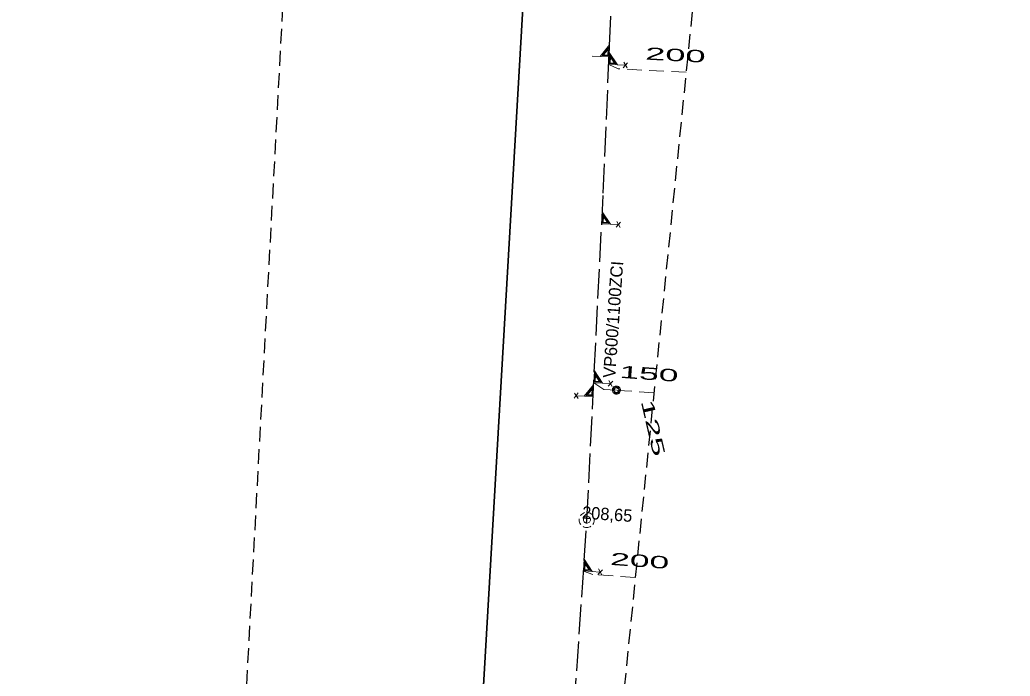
# Model space of a CAD drawing. Extents: x -744446 to -743929, y -1041261 to -1040599.
# Drawn here: x -744445.1 to -744380.7, y -1041003.3 to -1040960.6 of the extents above; entities that cross this region are included whole.
import ezdxf

# ---------------------------------------------------------------- set-up
doc = ezdxf.new("R2010")
doc.units = 0
doc.header["$LTSCALE"] = 0.32
doc.linetypes.add('LONG_DASHED', pattern=[7.5, 6, -1.5])
doc.linetypes.add('MEDIUM_DASHED', pattern=[4.5, 3, -1.5])
for name, color, linetype, lineweight in [('1', 7, 'MEDIUM_DASHED', 25), ('18', 7, 'Continuous', 13), ('20', 7, 'LONG_DASHED', 13), ('49', 7, 'MEDIUM_DASHED', 13)]:
    doc.layers.add(name, color=color, linetype=linetype, lineweight=lineweight)

msp = doc.modelspace()

# ---------------------------------------------------------------- linework, layer by layer
at = {"layer": '1'}
msp.add_lwpolyline([(-744438.077, -1041259.731), (-744438.679, -1041250.888), (-744445.125, -1041198.426), (-744434.434, -1041080.103), (-744426.87, -1040938.41), (-744425.446, -1040859.072), (-744414.192, -1040822.094), (-744390.076, -1040771.45), (-744357.118, -1040726.434), (-744307.278, -1040693.475), (-744241.36, -1040670.967), (-743937.498, -1040598.618), (-743928.655, -1040619.519), (-744129.684, -1040665.585), (-744218.109, -1040687.29), (-744311.358, -1040718.641), (-744361.198, -1040777.323), (-744391.745, -1040864.141), (-744411.355, -1041059.185), (-744416.379, -1041145.154), (-744432.569, -1041193.163), (-744432.047, -1041202.053), (-744422.803, -1041230.992), (-744424.813, -1041260.936)], close=True, dxfattribs=at)
at = {"layer": '18'}
for p, q in [((-744405.591, -1040963.438), (-744405.874, -1040963.761)), ((-744405.617, -1040963.775), (-744405.845, -1040963.394)), ((-744406.047, -1040973.806), (-744406.333, -1040974.127)), ((-744406.076, -1040974.143), (-744406.301, -1040973.76)), ((-744406.566, -1040984.143), (-744406.852, -1040984.464)), ((-744406.595, -1040984.48), (-744406.82, -1040984.097)), ((-744409.062, -1040985.256), (-744408.8, -1040984.898)), ((-744409.058, -1040984.917), (-744408.806, -1040985.265)), ((-744407.234, -1040996.401), (-744407.524, -1040996.718)), ((-744407.268, -1040996.738), (-744407.487, -1040996.351))]:
    msp.add_line(p, q, dxfattribs=at)
for points in [[(-744407.89, -1040963), (-744406.795, -1040963.047), (-744406.762, -1040962.276), (-744407.372, -1040963.022)], [(-744407.252, -1040962.976), (-744406.837, -1040962.994), (-744406.812, -1040962.429), (-744407.253, -1040962.976)], [(-744407.166, -1040962.933), (-744406.876, -1040962.945), (-744406.86, -1040962.574), (-744407.166, -1040962.934)], [(-744405.727, -1040963.592), (-744406.821, -1040963.545), (-744406.788, -1040962.776), (-744406.243, -1040963.57)], [(-744406.36, -1040963.515), (-744406.775, -1040963.497), (-744406.751, -1040962.932), (-744406.358, -1040963.515)], [(-744406.441, -1040963.465), (-744406.733, -1040963.452), (-744406.717, -1040963.08), (-744406.441, -1040963.466)], [(-744406.184, -1040973.959), (-744407.278, -1040973.904), (-744407.239, -1040973.135), (-744406.7, -1040973.933)], [(-744406.817, -1040973.878), (-744407.231, -1040973.857), (-744407.203, -1040973.291), (-744406.815, -1040973.878)], [(-744406.897, -1040973.826), (-744407.189, -1040973.812), (-744407.17, -1040973.44), (-744406.897, -1040973.827)], [(-744406.703, -1040984.296), (-744407.797, -1040984.241), (-744407.758, -1040983.472), (-744407.219, -1040984.27)], [(-744407.336, -1040984.215), (-744407.75, -1040984.194), (-744407.722, -1040983.628), (-744407.334, -1040984.215)], [(-744407.416, -1040984.163), (-744407.708, -1040984.149), (-744407.689, -1040983.777), (-744407.416, -1040984.164)], [(-744408.937, -1040985.084), (-744407.843, -1040985.139), (-744407.804, -1040984.369), (-744408.42, -1040985.11)], [(-744408.3, -1040985.065), (-744407.884, -1040985.086), (-744407.856, -1040984.522), (-744408.301, -1040985.065)], [(-744408.213, -1040985.023), (-744407.923, -1040985.037), (-744407.904, -1040984.667), (-744408.213, -1040985.025)], [(-744408.396, -1040992.69), (-744408.467, -1040992.718), (-744408.534, -1040992.757), (-744408.594, -1040992.805), (-744408.645, -1040992.862), (-744408.669, -1040992.896)], [(-744407.855, -1040992.873), (-744407.905, -1040992.815), (-744407.963, -1040992.765), (-744408.028, -1040992.724), (-744408.099, -1040992.695), (-744408.148, -1040992.681)], [(-744408.741, -1040993.082), (-744408.747, -1040993.159), (-744408.742, -1040993.236), (-744408.725, -1040993.311), (-744408.696, -1040993.382), (-744408.656, -1040993.448), (-744408.64, -1040993.47)], [(-744408.483, -1040993.599), (-744408.413, -1040993.63), (-744408.338, -1040993.649), (-744408.262, -1040993.656), (-744408.185, -1040993.651), (-744408.11, -1040993.634), (-744408.038, -1040993.606), (-744407.978, -1040993.571)], [(-744407.86, -1040993.459), (-744407.819, -1040993.394), (-744407.788, -1040993.324), (-744407.769, -1040993.249), (-744407.761, -1040993.173), (-744407.766, -1040993.096), (-744407.772, -1040993.061)], [(-744407.373, -1040996.552), (-744408.466, -1040996.479), (-744408.414, -1040995.711), (-744407.889, -1040996.518)], [(-744408.004, -1040996.46), (-744408.418, -1040996.432), (-744408.381, -1040995.868), (-744408.002, -1040996.46)], [(-744408.084, -1040996.408), (-744408.375, -1040996.388), (-744408.351, -1040996.017), (-744408.084, -1040996.409)]]:
    msp.add_lwpolyline(points, dxfattribs=at)
for points in [[(-744406.057, -1040984.722), (-744406.063, -1040984.666), (-744406.08, -1040984.613), (-744406.108, -1040984.564), (-744406.147, -1040984.523), (-744406.193, -1040984.491), (-744406.245, -1040984.469), (-744406.3, -1040984.458), (-744406.356, -1040984.46), (-744406.411, -1040984.473), (-744406.462, -1040984.498), (-744406.506, -1040984.533), (-744406.542, -1040984.576), (-744406.567, -1040984.626), (-744406.582, -1040984.681), (-744406.585, -1040984.737), (-744406.576, -1040984.792), (-744406.555, -1040984.845), (-744406.524, -1040984.891), (-744406.483, -1040984.93), (-744406.436, -1040984.96), (-744406.383, -1040984.979), (-744406.327, -1040984.986), (-744406.271, -1040984.982), (-744406.217, -1040984.965), (-744406.168, -1040984.938), (-744406.126, -1040984.9), (-744406.093, -1040984.855), (-744406.07, -1040984.804), (-744406.058, -1040984.749)], [(-744406.116, -1040984.725), (-744406.122, -1040984.676), (-744406.14, -1040984.63), (-744406.168, -1040984.589), (-744406.205, -1040984.556), (-744406.249, -1040984.534), (-744406.297, -1040984.522), (-744406.346, -1040984.522), (-744406.394, -1040984.534), (-744406.438, -1040984.557), (-744406.475, -1040984.59), (-744406.503, -1040984.631), (-744406.52, -1040984.678), (-744406.526, -1040984.727), (-744406.519, -1040984.776), (-744406.501, -1040984.822), (-744406.473, -1040984.862), (-744406.436, -1040984.895), (-744406.392, -1040984.917), (-744406.343, -1040984.929), (-744406.294, -1040984.928), (-744406.246, -1040984.916), (-744406.203, -1040984.892), (-744406.166, -1040984.859), (-744406.138, -1040984.818), (-744406.122, -1040984.771)], [(-744406.175, -1040984.729), (-744406.181, -1040984.687), (-744406.198, -1040984.649), (-744406.226, -1040984.618), (-744406.261, -1040984.595), (-744406.301, -1040984.584), (-744406.343, -1040984.584), (-744406.383, -1040984.596), (-744406.418, -1040984.619), (-744406.445, -1040984.651), (-744406.462, -1040984.689), (-744406.467, -1040984.73), (-744406.461, -1040984.772), (-744406.443, -1040984.809), (-744406.415, -1040984.841), (-744406.379, -1040984.863), (-744406.339, -1040984.874), (-744406.297, -1040984.873), (-744406.257, -1040984.86), (-744406.223, -1040984.837), (-744406.196, -1040984.804), (-744406.18, -1040984.766)], [(-744408.012, -1040993.142), (-744408.018, -1040993.09), (-744408.036, -1040993.04), (-744408.064, -1040992.996), (-744408.102, -1040992.959), (-744408.147, -1040992.932), (-744408.197, -1040992.916), (-744408.249, -1040992.911), (-744408.301, -1040992.918), (-744408.35, -1040992.937), (-744408.394, -1040992.967), (-744408.429, -1040993.006), (-744408.455, -1040993.051), (-744408.47, -1040993.102), (-744408.473, -1040993.154), (-744408.465, -1040993.206), (-744408.444, -1040993.254), (-744408.414, -1040993.297), (-744408.374, -1040993.332), (-744408.328, -1040993.356), (-744408.277, -1040993.37), (-744408.225, -1040993.372), (-744408.173, -1040993.362), (-744408.125, -1040993.34), (-744408.083, -1040993.308), (-744408.05, -1040993.268), (-744408.026, -1040993.221), (-744408.014, -1040993.17)]]:
    msp.add_lwpolyline(points, close=True, dxfattribs=at)
at = {"layer": '20', "lineweight": 25}
msp.add_line((-744410.659, -1041029.321), (-744408.243, -1040993.153), dxfattribs=at)
at = {"layer": '20', "linetype": 'Continuous', "lineweight": 35}
msp.add_lwpolyline([(-744429.62, -1041252.21), (-744428.789, -1041237.94), (-744437.959, -1041195.193), (-744423.3, -1041145.69), (-744417.879, -1041053.98), (-744409.949, -1040917.67), (-744407.76, -1040880.01), (-744407.219, -1040869.23), (-744404.395, -1040847.829), (-744400.25, -1040827.35), (-744393.491, -1040807.621), (-744384.879, -1040787.9), (-744372.238, -1040768.547), (-744361.26, -1040752.62), (-744345.317, -1040736.555), (-744330.739, -1040723.14), (-744312.333, -1040710.859), (-744294.67, -1040700.75), (-744274.728, -1040692.583), (-744254.699, -1040686.49), (-744133.87, -1040657.39), (-743953.289, -1040613.85), (-743946.017, -1040612.141)], dxfattribs=at)
at = {"layer": '20', "lineweight": 25}
msp.add_lwpolyline([(-744408.243, -1040993.153), (-744407.177, -1040971.928), (-744406.539, -1040956.977), (-744404.361, -1040919.606)], dxfattribs=at)
at = {"layer": '49'}
msp.add_line((-744403.886, -1040984.896), (-744406.321, -1040984.735), dxfattribs=at)
for points in [[(-744401.79, -1040964.043), (-744406.212, -1040963.839), (-744406.82, -1040963.551)], [(-744406.321, -1040984.735), (-744407.14, -1040984.681), (-744407.796, -1040984.247)], [(-744405.093, -1040996.896), (-744407.856, -1040996.707), (-744408.465, -1040996.485)]]:
    msp.add_lwpolyline(points, dxfattribs=at)

# ---------------------------------------------------------------- texts
at = {"layer": '1'}
for s, rotation, width, p in [('200 ', 357, 2.2, (-744404.465, -1040963.23)), ('150 ', 356, 2.15, (-744406.146, -1040983.918)), ('125 ', 283, 2.1, (-744404.742, -1040985.438)), ('200 ', 356, 2.15, (-744406.75, -1040996.082))]:
    msp.add_text(s, height=0.8, rotation=rotation, dxfattribs=dict(at, width=width)).set_placement(p)
for s, rotation, p in [('VP600/1100ZCI ', 86, (-744406.403, -1040983.956)), ('208,65', 356, (-744408.58, -1040993.069))]:
    msp.add_text(s, height=0.8, rotation=rotation, dxfattribs=at).set_placement(p)

doc.saveas('drawing.dxf')
